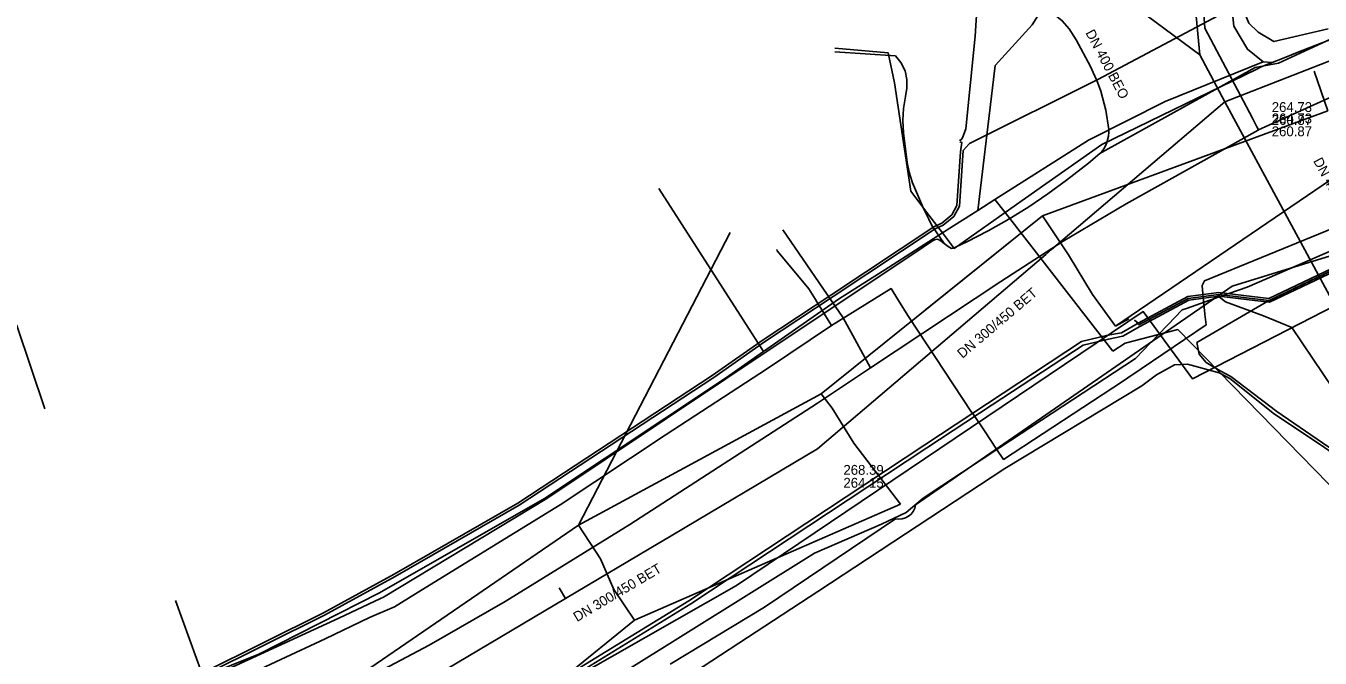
# Model space of a CAD drawing. Extents: x -600309 to -598967, y -1161267 to -1160292.
# Drawn here: x -599607.7 to -599502.5, y -1160557.4 to -1160506.1 of the extents above; entities that cross this region are included whole.
import ezdxf

# ---------------------------------------------------------------- set-up
doc = ezdxf.new("R2010")
doc.units = 0
for name, color, linetype in [('Vrstva 1', 7, 'Continuous'), ('Vrstva 12', 7, 'Continuous'), ('Vrstva 13', 7, 'Continuous'), ('Vrstva 16', 7, 'Continuous'), ('Vrstva 19', 7, 'Continuous'), ('Vrstva 4', 7, 'Continuous'), ('Vrstva 42', 7, 'Continuous'), ('Vrstva 44', 7, 'Continuous'), ('Vrstva 54', 7, 'Continuous'), ('Vrstva 55', 7, 'Continuous'), ('Vrstva 9', 7, 'Continuous')]:
    doc.layers.add(name, color=color, linetype=linetype)

msp = doc.modelspace()

# ---------------------------------------------------------------- linework, layer by layer
at = {"layer": 'Vrstva 1'}
msp.add_line((-599500.1, -1160531), (-599510.24, -1160512.25), dxfattribs=at)
at = {"layer": 'Vrstva 12'}
for points in [[(-599519.67, -1160514.71), (-599519.67, -1160514.49), (-599519.91, -1160512.92), (-599520.31, -1160511.39), (-599520.57, -1160510.64), (-599521.14, -1160509.36), (-599522.31, -1160507.22), (-599522.89, -1160506.32), (-599523.44, -1160505.66), (-599524.66, -1160504.67), (-599526.39, -1160503.22), (-599529.67, -1160500.53), (-599530.32, -1160500), (-599530.71, -1160499.68)], [(-599500.95, -1160506.84), (-599505.87, -1160509.1), (-599507.76, -1160509.46), (-599520.2, -1160516.32), (-599520.4, -1160516.44)], [(-599500.94, -1160506.9), (-599502.9, -1160507.67), (-599504.35, -1160508.24), (-599504.81, -1160508.43)], [(-599533.03, -1160523.75), (-599534.04, -1160522.28), (-599534.3, -1160521.78), (-599534.73, -1160520.92), (-599535.62, -1160518.83), (-599535.9, -1160517.96), (-599536.05, -1160517.18), (-599536.35, -1160514.75), (-599536.4, -1160513.77), (-599536.34, -1160512.78), (-599536.18, -1160511.82), (-599536.08, -1160511.12), (-599536.09, -1160510.42), (-599536.2, -1160509.72), (-599536.57, -1160509.06), (-599537.01, -1160508.52), (-599541.94, -1160508.17)], [(-599507.12, -1160509), (-599515.08, -1160512.21), (-599521.3, -1160515.37)], [(-599506.39, -1160509.05), (-599507.12, -1160509)], [(-599504.81, -1160508.43), (-599505.69, -1160508.77), (-599506.39, -1160509.05)], [(-599521.3, -1160515.37), (-599528.92, -1160520.18)], [(-599520.4, -1160516.44), (-599520.24, -1160516.27), (-599520.08, -1160516.05), (-599519.94, -1160515.81), (-599519.83, -1160515.56), (-599519.76, -1160515.34)], [(-599519.76, -1160515.34), (-599519.69, -1160515.03), (-599519.67, -1160514.71)], [(-599520.4, -1160516.44), (-599521.31, -1160517.22), (-599523.09, -1160518.62), (-599524.61, -1160519.73), (-599526.16, -1160520.77), (-599527.79, -1160521.77), (-599529.47, -1160522.72), (-599531.2, -1160523.61), (-599532.07, -1160524.03), (-599532.32, -1160524.14), (-599532.45, -1160524.16), (-599532.71, -1160523.99), (-599533.03, -1160523.75)], [(-599528.92, -1160520.18), (-599530.32, -1160521.07)], [(-599555.31, -1160557.93), (-599547.64, -1160553.3), (-599537.01, -1160546.11), (-599536.74, -1160546.14), (-599536.46, -1160546.12), (-599536.19, -1160546.04), (-599535.94, -1160545.91), (-599535.73, -1160545.73), (-599535.56, -1160545.51), (-599535.43, -1160545.26), (-599535.36, -1160544.99), (-599509.65, -1160527.22), (-599498.39, -1160523.75), (-599497.78, -1160523.5), (-599492.41, -1160521.02)], [(-599530.32, -1160521.07), (-599532.8, -1160522.65)], [(-599495.48, -1160521.7), (-599498.04, -1160522.79), (-599508.41, -1160527.29), (-599510.69, -1160528.09)], [(-599533.05, -1160522.81), (-599533.18, -1160522.89)], [(-599532.8, -1160522.65), (-599533.05, -1160522.81)], [(-599595.97, -1160560.5), (-599582.23, -1160554.18), (-599578.84, -1160552.6), (-599578.62, -1160552.47), (-599565.34, -1160544.46), (-599550.78, -1160534.74), (-599547.45, -1160532.52), (-599534.75, -1160524.04), (-599533.94, -1160523.5), (-599533.83, -1160523.46), (-599533.59, -1160523.41), (-599533.52, -1160523.42), (-599533.39, -1160523.47), (-599533.03, -1160523.75)], [(-599537.58, -1160525.69), (-599533.18, -1160522.89)], [(-599547.73, -1160532.53), (-599541.62, -1160528.27), (-599537.58, -1160525.69)], [(-599510.69, -1160528.09), (-599513.36, -1160529.03)], [(-599510.69, -1160528.09), (-599510.19, -1160528.5), (-599507.09, -1160529.64), (-599504.8, -1160530.57), (-599501.44, -1160535.55), (-599488.47, -1160556.93)], [(-599513.36, -1160529.03), (-599513.69, -1160529.15), (-599514.87, -1160530.37)], [(-599528.51, -1160540.33), (-599517.5, -1160533.08), (-599515.63, -1160531.15)], [(-599515.63, -1160531.15), (-599518.34, -1160531.84)], [(-599514.87, -1160530.37), (-599515.63, -1160531.15)], [(-599488.47, -1160556.93), (-599514.06, -1160530.75), (-599515.63, -1160531.15)], [(-599606.65, -1160564.32), (-599588.75, -1160557.1), (-599578.92, -1160552.13), (-599565.52, -1160544.47), (-599550.82, -1160534.69), (-599547.73, -1160532.53)], [(-599582.05, -1160571.71), (-599579.05, -1160570.45), (-599576.77, -1160569.87), (-599575.16, -1160568.63), (-599543.57, -1160548.9), (-599538.13, -1160546.56), (-599536.13, -1160545.6), (-599534.74, -1160544.44), (-599528.51, -1160540.33)]]:
    msp.add_lwpolyline(points, dxfattribs=at)
at = {"layer": 'Vrstva 13'}
msp.add_line((-599507.51, -1160514.53), (-599507.66, -1160514.21), dxfattribs=at)
for points in [[(-599344.9, -1160446.27), (-599352.28, -1160448.93), (-599363.59, -1160453.27), (-599376.64, -1160458.69), (-599385.7, -1160462.59), (-599402.72, -1160470.02), (-599420.24, -1160477.46), (-599444.43, -1160487.62), (-599456.17, -1160492.61), (-599471.63, -1160499.12), (-599478.53, -1160502.01), (-599498.26, -1160510.35), (-599507.51, -1160514.53)], [(-599520.42, -1160499.12), (-599524.09, -1160503.13), (-599525.88, -1160506), (-599528.89, -1160509.29), (-599530.32, -1160521.07)], [(-599507.66, -1160514.21), (-599507.98, -1160513.58), (-599511.87, -1160506.25), (-599512.04, -1160503.46)], [(-599509.74, -1160503.73), (-599509.51, -1160506.11)], [(-599509.51, -1160506.11), (-599508.4, -1160507.97), (-599507.12, -1160509)], [(-599541.92, -1160507.88), (-599537.59, -1160508.27), (-599537.09, -1160510.7), (-599535.75, -1160519.49), (-599534.28, -1160521.44), (-599533.18, -1160522.89)], [(-599506.39, -1160509.05), (-599507.27, -1160509.41), (-599507.64, -1160509.59), (-599520.22, -1160515.7), (-599523.96, -1160518.34), (-599524.78, -1160518.91), (-599528.09, -1160521.24)], [(-599507.51, -1160514.53), (-599507.53, -1160514.54), (-599518.26, -1160520.52), (-599523.38, -1160523.57), (-599528.43, -1160526.85), (-599539.02, -1160533.85), (-599543.33, -1160536.71), (-599558.58, -1160546.59), (-599568.71, -1160552.83), (-599574.9, -1160556.39), (-599584.5, -1160561.46), (-599590.84, -1160564.32), (-599595.36, -1160566.36), (-599600.89, -1160568.66), (-599614.59, -1160574.46)], [(-599547.73, -1160532.53), (-599556.24, -1160519.29)], [(-599528.92, -1160520.18), (-599528.09, -1160521.24)], [(-599533.18, -1160522.89), (-599532.44, -1160523.85), (-599532.22, -1160524.15), (-599528.09, -1160521.24)], [(-599519.34, -1160532.51), (-599528.09, -1160521.24)], [(-599539.02, -1160533.85), (-599541.26, -1160529.78), (-599546.15, -1160522.64)], [(-599606.12, -1160537.17), (-599608.4, -1160530.4), (-599612.9, -1160535.8), (-599613.88, -1160537.03), (-599618.29, -1160541.49), (-599620.49, -1160542.49)], [(-599518.34, -1160531.84), (-599519.34, -1160532.51)], [(-599590.84, -1160564.32), (-599593.23, -1160559.04), (-599595.52, -1160552.74)]]:
    msp.add_lwpolyline(points, dxfattribs=at)
at = {"layer": 'Vrstva 16'}
msp.add_lwpolyline([(-599543.07, -1160529), (-599543.19, -1160528.81), (-599543.51, -1160528.31), (-599544.05, -1160527.44), (-599545.92, -1160525.19), (-599546.62, -1160524.36), (-599546.65, -1160524.25)], dxfattribs=at)
at = {"layer": 'Vrstva 19'}
for points in [[(-599497.98, -1160521.09), (-599511.89, -1160526.79), (-599512.08, -1160527.17), (-599512.02, -1160527.85), (-599511.85, -1160529.5), (-599511.76, -1160530.36), (-599517.03, -1160533.92), (-599518.13, -1160534.66), (-599518.56, -1160534.95), (-599528.21, -1160541.29), (-599528.78, -1160540.45), (-599529.77, -1160538.98), (-599530.78, -1160537.48), (-599530.81, -1160537.45), (-599535.94, -1160529.67), (-599536.81, -1160528.31), (-599537.36, -1160527.42), (-599542.19, -1160530.42), (-599547.41, -1160533.9), (-599555.72, -1160539.33), (-599564.25, -1160544.98), (-599575.22, -1160551.73), (-599577.71, -1160553.26), (-599579.74, -1160554.14), (-599583.34, -1160555.86), (-599597.77, -1160562.58)], [(-599542.19, -1160530.42), (-599542.46, -1160529.98), (-599543.07, -1160529)]]:
    msp.add_lwpolyline(points, dxfattribs=at)
at = {"layer": 'Vrstva 42'}
for points in [[(-599580.25, -1160468.12), (-599578.54, -1160466.46), (-599576.06, -1160463.28), (-599575.67, -1160462.74), (-599574.1, -1160464.06), (-599573.3, -1160464.75), (-599571.35, -1160466.45), (-599566.34, -1160470.66), (-599560.31, -1160475.74), (-599552.84, -1160481.98), (-599546.61, -1160487.21), (-599545.9, -1160487.81), (-599539.95, -1160492.85), (-599534.08, -1160497.77), (-599530.42, -1160501.02), (-599530.2, -1160501.78), (-599530.53, -1160506.91), (-599531.27, -1160514.43), (-599531.56, -1160515.17), (-599531.69, -1160515.36), (-599531.79, -1160515.36)], [(-599517.58, -1160529.98), (-599517.29, -1160530.23), (-599513.25, -1160528.06), (-599510.71, -1160527.74), (-599506.67, -1160528.23), (-599498.18, -1160524.18), (-599495.77, -1160524.02), (-599482.38, -1160518.46), (-599460.17, -1160509.08), (-599458.94, -1160508.36), (-599451.05, -1160505.22), (-599445.13, -1160502.64), (-599442.76, -1160499.07), (-599442.44, -1160498.8), (-599433.69, -1160494.99), (-599418.03, -1160488.37), (-599410.63, -1160484.74), (-599406.02, -1160482.91)], [(-599517.58, -1160529.98), (-599517.29, -1160530.23), (-599513.25, -1160528.06), (-599510.71, -1160527.74), (-599506.67, -1160528.23), (-599498.18, -1160524.18), (-599495.77, -1160524.02), (-599482.38, -1160518.46), (-599460.17, -1160509.08), (-599458.94, -1160508.36), (-599451.05, -1160505.22), (-599445.13, -1160502.64), (-599442.76, -1160499.07), (-599442.44, -1160498.8), (-599433.69, -1160494.99), (-599418.03, -1160488.37), (-599410.63, -1160484.74), (-599406.02, -1160482.91)], [(-599502.58, -1160499.2), (-599506.19, -1160500.03), (-599506.4, -1160500.1), (-599507.71, -1160500.54), (-599508, -1160500.64), (-599508.8, -1160500.76), (-599508.73, -1160503.79), (-599508.73, -1160504.01), (-599509.41, -1160504.53), (-599520.55, -1160510.42), (-599530.98, -1160515.64), (-599531.5, -1160516.2), (-599531.8, -1160520.72), (-599532.26, -1160521.55), (-599533.12, -1160522.25), (-599533.78, -1160522.57), (-599542.06, -1160528.06), (-599547.64, -1160531.75), (-599551.77, -1160534.64), (-599567.59, -1160545), (-599577.65, -1160550.79), (-599583.39, -1160553.94), (-599593.15, -1160558.79)], [(-599502.42, -1160499.48), (-599506.26, -1160500.28), (-599507.56, -1160500.54), (-599507.71, -1160500.54), (-599508.81, -1160500.55), (-599508.93, -1160501.15), (-599508.73, -1160503.79), (-599508.65, -1160504.94), (-599508.27, -1160505.84), (-599507.52, -1160506.59), (-599506.25, -1160507.35), (-599501.84, -1160506.32)], [(-599506.61, -1160528.53), (-599498.1, -1160524.48), (-599495.7, -1160524.32), (-599482.26, -1160518.74), (-599460.03, -1160509.34), (-599458.81, -1160508.63), (-599458.92, -1160507.99), (-599457.85, -1160504.47), (-599456.35, -1160502.18)], [(-599506.61, -1160528.53), (-599498.1, -1160524.48), (-599495.7, -1160524.32), (-599482.26, -1160518.74), (-599460.03, -1160509.34), (-599458.81, -1160508.63), (-599458.92, -1160507.99), (-599457.85, -1160504.47), (-599456.35, -1160502.18)], [(-599531.78, -1160515.49), (-599531.6, -1160515.55), (-599531.71, -1160516.31), (-599532, -1160520.66), (-599532.42, -1160521.43), (-599533.22, -1160522.09), (-599533.88, -1160522.39), (-599542.17, -1160527.9), (-599547.76, -1160531.59), (-599551.89, -1160534.48), (-599567.69, -1160544.84), (-599577.75, -1160550.61), (-599583.49, -1160553.76), (-599593.23, -1160558.61)], [(-599498.14, -1160524.33), (-599506.64, -1160528.38), (-599507.8, -1160528.24), (-599510.71, -1160527.89), (-599513.2, -1160528.21), (-599517.22, -1160530.36), (-599517.58, -1160529.98)], [(-599666.89, -1160598.93), (-599646, -1160593.56), (-599627.02, -1160588.71), (-599626.05, -1160588.6), (-599620.91, -1160587.09), (-599619.18, -1160585.95), (-599608.04, -1160583.08), (-599604.83, -1160581.69), (-599604.22, -1160580.43), (-599601.4, -1160578.74), (-599583.99, -1160571.18), (-599581.42, -1160568.83), (-599564.55, -1160559.73), (-599553.62, -1160553.03), (-599534.45, -1160540.36), (-599529.13, -1160536.86), (-599521.75, -1160532), (-599519.69, -1160531.51), (-599518.53, -1160531.29), (-599517.15, -1160530.5), (-599513.15, -1160528.35), (-599510.71, -1160528.04), (-599507.8, -1160528.39), (-599506.61, -1160528.53)], [(-599666.89, -1160598.93), (-599646, -1160593.56), (-599627.02, -1160588.71), (-599626.05, -1160588.6), (-599620.91, -1160587.09), (-599619.18, -1160585.95), (-599608.04, -1160583.08), (-599604.83, -1160581.69), (-599604.22, -1160580.43), (-599601.4, -1160578.74), (-599583.99, -1160571.18), (-599581.42, -1160568.83), (-599564.55, -1160559.73), (-599553.62, -1160553.03), (-599534.45, -1160540.36), (-599529.13, -1160536.86), (-599521.75, -1160532), (-599519.69, -1160531.51), (-599518.53, -1160531.29), (-599517.15, -1160530.5), (-599513.15, -1160528.35), (-599510.71, -1160528.04), (-599507.8, -1160528.39), (-599506.61, -1160528.53)], [(-599517.58, -1160529.98), (-599517.29, -1160530.23), (-599518.63, -1160531.01), (-599519.75, -1160531.21), (-599521.87, -1160531.72), (-599534.61, -1160540.11), (-599553.78, -1160552.77), (-599564.7, -1160559.47), (-599581.6, -1160568.59), (-599584.15, -1160570.92), (-599601.54, -1160578.48), (-599604.46, -1160580.21), (-599605.05, -1160581.46), (-599608.14, -1160582.8), (-599619.3, -1160585.67), (-599621.03, -1160586.81), (-599626.13, -1160588.31), (-599627.1, -1160588.42), (-599646.07, -1160593.27), (-599666.96, -1160598.64)], [(-599517.58, -1160529.98), (-599517.29, -1160530.23), (-599518.63, -1160531.01), (-599519.75, -1160531.21), (-599521.87, -1160531.72), (-599534.61, -1160540.11), (-599553.78, -1160552.77), (-599564.7, -1160559.47), (-599581.6, -1160568.59), (-599584.15, -1160570.92), (-599601.54, -1160578.48), (-599604.46, -1160580.21), (-599605.05, -1160581.46), (-599608.14, -1160582.8), (-599619.3, -1160585.67), (-599621.03, -1160586.81), (-599626.13, -1160588.31), (-599627.1, -1160588.42), (-599646.07, -1160593.27), (-599666.96, -1160598.64)], [(-599518.04, -1160529.87), (-599519.11, -1160530.47)]]:
    msp.add_lwpolyline(points, dxfattribs=at)
at = {"layer": 'Vrstva 44'}
for points in [[(-599510.61, -1160534.09), (-599511.75, -1160533.43), (-599512.31, -1160532.75), (-599512.52, -1160531.8), (-599506.73, -1160528.44), (-599498.05, -1160524.3), (-599490.95, -1160521.48), (-599482.94, -1160517.97), (-599472.45, -1160513.7), (-599462.86, -1160509.7), (-599452.58, -1160505.46), (-599446.03, -1160502.68), (-599437.8, -1160499.11), (-599428.89, -1160495.31), (-599417.52, -1160490.29), (-599411.94, -1160488.21), (-599405.84, -1160485.59)], [(-599510.7, -1160534.27), (-599513.26, -1160533.56), (-599514.33, -1160533.61), (-599515.78, -1160534.41), (-599516.98, -1160535.3), (-599528.11, -1160542.03), (-599543.31, -1160552.02), (-599556.94, -1160560.92), (-599564.85, -1160565.34), (-599583.27, -1160574.73), (-599593.12, -1160579.54), (-599605.71, -1160585.22), (-599609.46, -1160586.11), (-599616.82, -1160588.83), (-599618.48, -1160589.83), (-599619.53, -1160590.52), (-599619.65, -1160590.6), (-599619.68, -1160591.14), (-599619.48, -1160591.74)], [(-599510.7, -1160534.27), (-599509.83, -1160534.73), (-599506.2, -1160537.61), (-599502.41, -1160540.12), (-599500.26, -1160541.61), (-599497.66, -1160543.76), (-599497.17, -1160544.11), (-599496.79, -1160544.51), (-599495.4, -1160547.28), (-599492.84, -1160551.29), (-599489.57, -1160557.93), (-599485.84, -1160564.43), (-599482.39, -1160570.67), (-599479.35, -1160576.44), (-599472.98, -1160589.51), (-599470.33, -1160596.14), (-599468.55, -1160600.37), (-599466.17, -1160607.3), (-599464.7, -1160612.42), (-599463.4, -1160616.83)], [(-599510.61, -1160534.09), (-599509.74, -1160534.55), (-599506.02, -1160537.41), (-599502.3, -1160539.95), (-599500.19, -1160541.37), (-599497.62, -1160543.48), (-599497.02, -1160543.88), (-599496.57, -1160544.44), (-599495.08, -1160547.12), (-599492.66, -1160551.17), (-599489.42, -1160557.83), (-599485.65, -1160564.26), (-599482.13, -1160570.54), (-599479.13, -1160576.36), (-599472.79, -1160589.4), (-599470.1, -1160596.01), (-599468.39, -1160600.29), (-599465.91, -1160607.21), (-599464.51, -1160612.36), (-599463.22, -1160616.72)]]:
    msp.add_lwpolyline(points, dxfattribs=at)
at = {"layer": 'Vrstva 54'}
for points in [[(-599501.86, -1160512.97), (-599502.98, -1160509.75)], [(-599525.04, -1160521.51), (-599501.86, -1160512.97)], [(-599500.3, -1160517.66), (-599519.11, -1160530.47)], [(-599543.05, -1160535.97), (-599525.04, -1160521.51)], [(-599534.55, -1160529.14), (-599525.04, -1160521.51)], [(-599522.95, -1160524.68), (-599525.04, -1160521.51)], [(-599562.75, -1160546.64), (-599550.43, -1160522.85)], [(-599521, -1160527.9), (-599522.95, -1160524.68)], [(-599519.11, -1160530.47), (-599521, -1160527.9)], [(-599562.75, -1160546.64), (-599543.05, -1160535.97)], [(-599542.15, -1160537.12), (-599543.05, -1160535.97)], [(-599540.38, -1160539.98), (-599542.15, -1160537.12)], [(-599536.59, -1160544.93), (-599540.38, -1160539.98)], [(-599536.59, -1160544.93), (-599558.21, -1160554.34)], [(-599581.61, -1160559.54), (-599562.75, -1160546.64)], [(-599560.97, -1160549.36), (-599562.75, -1160546.64)], [(-599559.88, -1160551.85), (-599560.97, -1160549.36)], [(-599558.21, -1160554.34), (-599559.88, -1160551.85)], [(-599558.21, -1160554.34), (-599576.89, -1160569.51)]]:
    msp.add_lwpolyline(points, dxfattribs=at)
at = {"layer": 'Vrstva 55'}
msp.add_lwpolyline([(-599683.03, -1160601.17), (-599683.18, -1160599.83), (-599651.44, -1160592.06), (-599650.77, -1160593.12), (-599650.29, -1160591.81), (-599622.16, -1160585.67), (-599620.81, -1160585.45), (-599610.1, -1160582.19), (-599608.78, -1160582.26), (-599596.47, -1160577.71), (-599585.17, -1160571.6), (-599585.4, -1160570.82), (-599584.25, -1160571.09), (-599549.91, -1160551.54), (-599516.86, -1160529.28), (-599512.86, -1160534.75), (-599497.37, -1160526.78), (-599489.12, -1160522.63), (-599486.71, -1160527.61)], dxfattribs=at)
at = {"layer": 'Vrstva 9'}
for p, q in [((-599539.75, -1160488.03), (-599512.26, -1160508.42)), ((-599510.24, -1160512.25), (-599512.26, -1160508.42)), ((-599564.34, -1160551.73), (-599563.82, -1160552.59))]:
    msp.add_line(p, q, dxfattribs=at)
for points in [[(-599512.26, -1160508.42), (-599514.16, -1160488.41), (-599514.63, -1160483.42), (-599516.45, -1160464.22), (-599516.73, -1160461.32), (-599517, -1160458.43)], [(-599510.24, -1160512.25), (-599501.35, -1160508.78), (-599490.45, -1160504.52), (-599490.19, -1160504.42), (-599483.55, -1160501.83), (-599473.7, -1160497.98)], [(-599543.33, -1160540.43), (-599524.79, -1160524.64), (-599524.31, -1160524.23), (-599510.24, -1160512.25)], [(-599577.08, -1160560.46), (-599563.82, -1160552.59), (-599556.16, -1160548.04), (-599556.09, -1160548), (-599543.33, -1160540.43)]]:
    msp.add_lwpolyline(points, dxfattribs=at)

# ---------------------------------------------------------------- texts
at = {"layer": 'Vrstva 12'}
for s, rotation, p in [('DN 400 BEO', 297.8078, (-599521.58, -1160506.63)), ('DN 300/450 BET', 40.3935, (-599531.56, -1160533.13)), ('DN 300/450 BET', 30.6646, (-599562.88, -1160554.51))]:
    msp.add_text(s, height=0.8, rotation=rotation, dxfattribs=at).set_placement(p)
for s, p in [('264.73', (-599506.42, -1160513.07)), ('264.73', (-599506.42, -1160513.99)), ('260.87', (-599506.42, -1160514.12)), ('260.87', (-599506.42, -1160515.04)), ('268.39', (-599541.23, -1160542.54)), ('264.15', (-599541.23, -1160543.59))]:
    msp.add_text(s, height=0.8, dxfattribs=at).set_placement(p)
at = {"layer": 'Vrstva 4'}
msp.add_text('DN 400 KAM', height=0.8, rotation=298.4045, dxfattribs=at).set_placement((-599503.07, -1160517.04))

doc.saveas('drawing.dxf')
